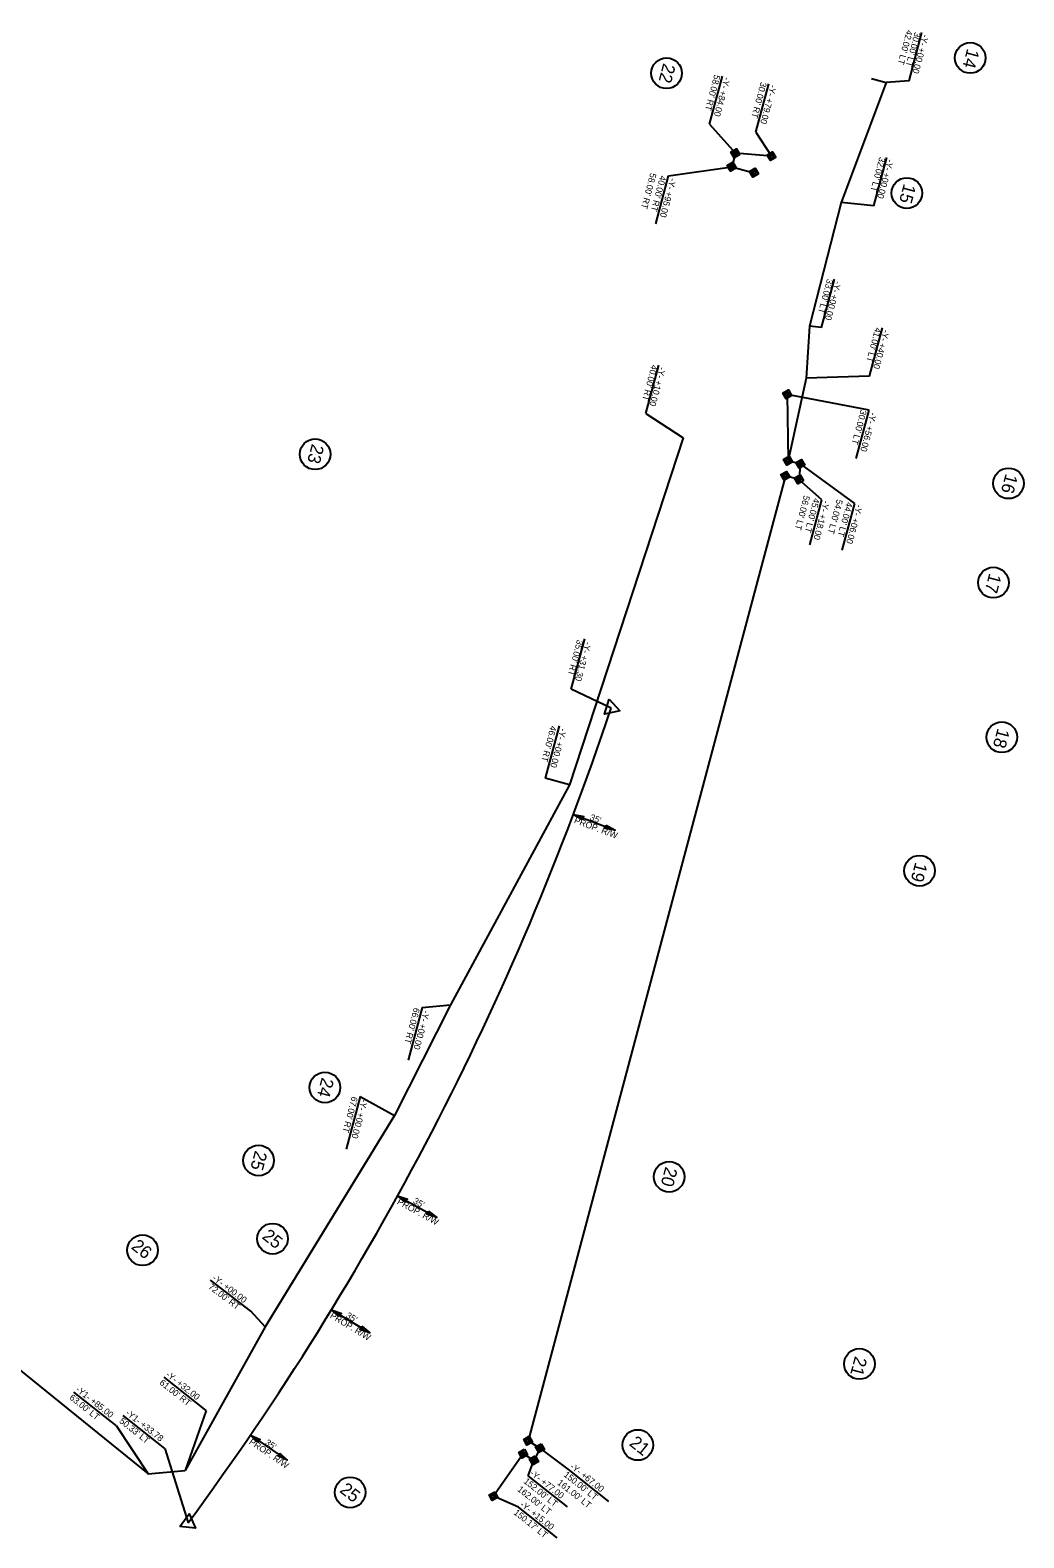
# Model space of a CAD drawing. Extents: x 1779796 to 1783527, y 810952 to 815815.
# Drawn here: x 1782441 to 1783220, y 814388 to 815570 of the extents above; entities that cross this region are included whole.
import ezdxf

# ---------------------------------------------------------------- set-up
doc = ezdxf.new("R2010")
doc.units = 0
for name, color, linetype in [('Prop Dimension', 7, 'Continuous'), ('Prop Dimension Text', 7, 'Continuous'), ('Prop Easement Construction', 7, 'Continuous'), ('Prop Easement Construction Station Offsets', 7, 'Continuous'), ('Prop Easement Permanent Utility', 7, 'Continuous'), ('Prop Easement Permanent Utility Station Offsets', 7, 'Continuous'), ('Prop Parcel Number CELL', 7, 'Continuous'), ('Prop Parcel Number Text', 7, 'Continuous'), ('Prop ROW Marker CELL', 7, 'Continuous'), ('Prop ROW Permanent Easement CELL', 7, 'Continuous'), ('Prop ROW RW Lines', 7, 'Continuous'), ('Prop ROW Station Offsets', 7, 'Continuous'), ('Prop Terminator CELL', 7, 'Continuous')]:
    doc.layers.add(name, color=color, linetype=linetype)

msp = doc.modelspace()

# ---------------------------------------------------------------- linework, layer by layer
at = {"layer": 'Prop Dimension'}
for p, q in [((1782866.5, 814955.2), (1782899.2, 814942.8)), ((1782728.7, 814656.4), (1782759.3, 814639.5)), ((1782676.9, 814567.2), (1782706.8, 814549)), ((1782613.3, 814468.9), (1782642.2, 814449.2))]:
    msp.add_line(p, q, dxfattribs=at)
at = {"layer": 'Prop Easement Construction'}
for p, q in [((1783100, 815531.7), (1783111.6, 815528.6)), ((1783111.6, 815528.6), (1783076.2, 815434.6)), ((1783076.2, 815434.6), (1783051.4, 815337.7)), ((1783051.4, 815337.7), (1783048.8, 815297)), ((1783048.8, 815297), (1783034.7, 815232.4)), ((1782952.5, 815250.2), (1782863.4, 814978.5)), ((1782863.4, 814978.5), (1782770, 814806)), ((1782770, 814806), (1782726.1, 814719.3)), ((1782726.1, 814719.3), (1782624.9, 814553.7)), ((1782354.4, 814583), (1782533.2, 814438.6)), ((1782624.9, 814553.7), (1782562.2, 814441.3)), ((1782533.2, 814438.6), (1782562.2, 814441.3))]:
    msp.add_line(p, q, dxfattribs=at)
at = {"layer": 'Prop Easement Construction Station Offsets'}
for p, q in [((1783129.5, 815530), (1783139.6, 815567.9)), ((1783129.5, 815530), (1783111.6, 815528.6)), ((1783101.9, 815432.1), (1783112, 815470)), ((1783101.9, 815432.1), (1783076.2, 815434.6)), ((1783060.9, 815336.7), (1783071, 815374.6)), ((1783060.9, 815336.7), (1783051.4, 815337.7)), ((1783098.6, 815298.5), (1783108.8, 815336.4)), ((1782923.3, 815269.4), (1782933.4, 815307.3)), ((1783098.6, 815298.5), (1783048.8, 815297)), ((1782923.3, 815269.4), (1782952.5, 815250.2)), ((1782855.2, 815024.7), (1782844.2, 814983.5)), ((1782863.4, 814978.5), (1782844.2, 814983.5)), ((1782748, 814803.9), (1782737, 814762.6)), ((1782748, 814803.9), (1782770, 814806)), ((1782699.4, 814734.2), (1782688.4, 814693)), ((1782699.4, 814734.2), (1782726.1, 814719.3)), ((1782613.7, 814566.1), (1782581.9, 814590.3)), ((1782624.9, 814553.7), (1782613.7, 814566.1)), ((1782578.6, 814488.2), (1782545.6, 814514.3)), ((1782508, 814476.5), (1782475, 814502.6)), ((1782578.6, 814488.2), (1782562.2, 814441.3))]:
    msp.add_line(p, q, dxfattribs=at)
msp.add_lwpolyline([(1782508, 814476.5), (1782533.2, 814438.6)], dxfattribs=at)
at = {"layer": 'Prop Easement Permanent Utility'}
for p, q in [((1782993.4, 815473.2), (1782990.5, 815462.6)), ((1783021.7, 815470.8), (1782993.4, 815473.2)), ((1782990.5, 815462.6), (1783007.9, 815457.9)), ((1783034.1, 815284.3), (1783034.7, 815232.4)), ((1783034.7, 815232.4), (1783044.4, 815229.8)), ((1783044.4, 815229.8), (1783043.2, 815217.7)), ((1783032.6, 815220.5), (1782830.9, 814464.5)), ((1783043.2, 815217.7), (1783032.6, 815220.5)), ((1782830.9, 814464.5), (1782840.3, 814458.7)), ((1782840.3, 814458.7), (1782835.5, 814449.1)), ((1782827, 814454.4), (1782803.9, 814421.2)), ((1782835.5, 814449.1), (1782827, 814454.4))]:
    msp.add_line(p, q, dxfattribs=at)
at = {"layer": 'Prop Easement Permanent Utility Station Offsets'}
for p, q in [((1782973.2, 815496), (1782983.2, 815533.5)), ((1783009.4, 815489.7), (1783019.5, 815527.6)), ((1782931, 815417.9), (1782941, 815455.4)), ((1783088.1, 815234.1), (1783098.2, 815272)), ((1783051.7, 815166.4), (1783061.1, 815201.8)), ((1783077.2, 815162.2), (1783086.9, 815198.7)), ((1782861.8, 814412.7), (1782831.1, 814437)), ((1782894.2, 814417), (1782862.4, 814442.2)), ((1782853.7, 814388.5), (1782823.3, 814412.5))]:
    msp.add_line(p, q, dxfattribs=at)
for points in [[(1782973.2, 815496), (1782993.4, 815473.2)], [(1783009.4, 815489.7), (1783021.7, 815470.8)], [(1782941, 815455.4), (1782990.5, 815462.6)], [(1783098.2, 815272), (1783034.1, 815284.3)], [(1783086.9, 815198.7), (1783044.4, 815229.8)], [(1783061.1, 815201.8), (1783043.2, 815217.7)], [(1782862.4, 814442.2), (1782840.3, 814458.7)], [(1782831.1, 814437), (1782835.5, 814449.1)], [(1782823.3, 814412.5), (1782803.9, 814421.2)]]:
    msp.add_lwpolyline(points, dxfattribs=at)
at = {"layer": 'Prop Parcel Number CELL'}
for p, q in [((1783177.5, 815547.9), (1783177.5, 815547.9)), ((1782939.5, 815535.9), (1782939.5, 815535.9)), ((1783127.8, 815442), (1783127.8, 815442)), ((1782664, 815237.4), (1782664, 815237.4)), ((1783207.5, 815214.6), (1783207.5, 815214.6)), ((1783195.6, 815136.8), (1783195.6, 815136.8)), ((1783202.2, 815015.7), (1783202.2, 815015.7)), ((1783137.8, 814911.1), (1783137.8, 814911.1)), ((1782671.7, 814741.3), (1782671.7, 814741.3)), ((1782619.7, 814684.1), (1782619.7, 814684.1)), ((1782941.5, 814671.3), (1782941.5, 814671.3)), ((1782630.7, 814622.8), (1782630.7, 814622.8)), ((1782528.8, 814613.8), (1782528.8, 814613.8)), ((1783090.6, 814524.7), (1783090.6, 814524.7)), ((1782916.9, 814461.2), (1782916.9, 814461.2)), ((1782691.5, 814424.1), (1782691.5, 814424.1))]:
    msp.add_line(p, q, dxfattribs=at)
for centre in [(1783177.5, 815547.9), (1782939.5, 815535.9), (1783127.8, 815442), (1782664, 815237.4), (1783207.5, 815214.6), (1783195.6, 815136.8), (1783202.2, 815015.7), (1783137.8, 814911.1), (1782671.7, 814741.3), (1782619.7, 814684.1), (1782941.5, 814671.3), (1782630.7, 814622.8), (1782528.8, 814613.8), (1783090.6, 814524.7), (1782916.9, 814461.2), (1782691.5, 814424.1)]:
    msp.add_circle(centre, 12, dxfattribs=at)
at = {"layer": 'Prop ROW Marker CELL'}
for p, q in [((1782993.4, 815473.2), (1782993.4, 815473.2)), ((1782990.5, 815462.6), (1782990.5, 815462.6)), ((1783021.7, 815470.8), (1783021.7, 815470.8)), ((1783007.9, 815457.9), (1783007.9, 815457.9)), ((1783034.1, 815284.3), (1783034.1, 815284.3)), ((1783034.7, 815232.4), (1783034.7, 815232.4)), ((1783044.4, 815229.8), (1783044.4, 815229.8)), ((1783032.6, 815220.5), (1783032.6, 815220.5)), ((1783043.2, 815217.7), (1783043.2, 815217.7)), ((1782896.1, 815038.5), (1782896.1, 815038.5)), ((1782830.9, 814464.5), (1782830.9, 814464.5)), ((1782840.3, 814458.7), (1782840.3, 814458.7)), ((1782827, 814454.4), (1782827, 814454.4)), ((1782835.5, 814449.1), (1782835.5, 814449.1)), ((1782803.9, 814421.2), (1782803.9, 814421.2)), ((1782564.5, 814400.3), (1782564.5, 814400.3))]:
    msp.add_line(p, q, dxfattribs=at)
for points in [[(1782894.5, 815045.6), (1782902.9, 815036.4), (1782890.8, 815033.7)], [(1782557.9, 814397.4), (1782565.3, 814407.4), (1782570.3, 814396)]]:
    msp.add_lwpolyline(points, close=True, dxfattribs=at)
at = {"layer": 'Prop ROW Permanent Easement CELL'}
for points in [[(1782996.8, 815472.3), (1782992.4, 815469.7), (1782989.9, 815474.1), (1782994.3, 815476.7)], [(1782995.1, 815472.7), (1782992.9, 815471.5), (1782991.6, 815473.7), (1782993.8, 815475)], [(1783025.2, 815469.9), (1783020.8, 815467.4), (1783018.2, 815471.8), (1783022.6, 815474.3)], [(1783023.4, 815470.4), (1783021.2, 815469.1), (1783020, 815471.3), (1783022.2, 815472.6)], [(1782994, 815461.7), (1782989.6, 815459.1), (1782987, 815463.5), (1782991.4, 815466.1)], [(1782992.3, 815462.1), (1782990.1, 815460.8), (1782988.8, 815463), (1782991, 815464.3)], [(1783011.4, 815457), (1783007, 815454.5), (1783004.4, 815458.9), (1783008.8, 815461.4)], [(1783009.6, 815457.5), (1783007.4, 815456.2), (1783006.2, 815458.4), (1783008.4, 815459.7)], [(1783037.5, 815283.4), (1783033.1, 815280.9), (1783030.6, 815285.3), (1783035, 815287.8)], [(1783035.8, 815283.9), (1783033.6, 815282.6), (1783032.3, 815284.8), (1783034.5, 815286.1)], [(1783038.2, 815231.5), (1783033.8, 815228.9), (1783031.2, 815233.3), (1783035.6, 815235.9)], [(1783036, 815219.6), (1783031.6, 815217.1), (1783029.1, 815221.5), (1783033.5, 815224)], [(1783036.4, 815231.9), (1783034.2, 815230.7), (1783033, 815232.9), (1783035.2, 815234.2)], [(1783047.8, 815228.9), (1783043.4, 815226.4), (1783040.9, 815230.8), (1783045.3, 815233.3)], [(1783046.1, 815229.4), (1783043.9, 815228.1), (1783042.6, 815230.3), (1783044.8, 815231.6)], [(1783034.3, 815220.1), (1783032.1, 815218.8), (1783030.8, 815221), (1783033, 815222.3)], [(1783046.7, 815216.8), (1783042.3, 815214.2), (1783039.7, 815218.6), (1783044.1, 815221.2)], [(1783044.9, 815217.2), (1783042.7, 815216), (1783041.4, 815218.2), (1783043.6, 815219.4)], [(1782831.9, 814468), (1782834.4, 814463.5), (1782830, 814461), (1782827.5, 814465.5)], [(1782828, 814457.9), (1782830.5, 814453.4), (1782826.1, 814450.9), (1782823.6, 814455.3)], [(1782827.5, 814456.1), (1782828.8, 814453.9), (1782826.6, 814452.7), (1782825.3, 814454.9)], [(1782831.4, 814466.2), (1782832.7, 814464), (1782830.5, 814462.8), (1782829.2, 814465)], [(1782841.3, 814462.2), (1782843.8, 814457.8), (1782839.3, 814455.3), (1782836.8, 814459.7)], [(1782840.8, 814460.5), (1782842, 814458.3), (1782839.8, 814457), (1782838.6, 814459.2)], [(1782836.5, 814452.6), (1782839, 814448.2), (1782834.6, 814445.6), (1782832.1, 814450.1)], [(1782836, 814450.8), (1782837.3, 814448.6), (1782835.1, 814447.4), (1782833.8, 814449.6)], [(1782804.8, 814424.6), (1782807.3, 814420.2), (1782802.9, 814417.7), (1782800.4, 814422.1)], [(1782804.3, 814422.9), (1782805.6, 814420.7), (1782803.4, 814419.4), (1782802.1, 814421.6)]]:
    msp.add_lwpolyline(points, close=True, dxfattribs=at)
at = {"layer": 'Prop ROW RW Lines'}
msp.add_arc((1780718.8, 815764.3), 2295, 323.5346, 341.5656, dxfattribs=at)
at = {"layer": 'Prop ROW Station Offsets'}
for p, q in [((1782864.8, 815053.3), (1782875.4, 815092.8)), ((1782896.1, 815038.5), (1782864.8, 815053.3)), ((1782546.3, 814458.4), (1782513.5, 814484.4))]:
    msp.add_line(p, q, dxfattribs=at)
msp.add_lwpolyline([(1782546.3, 814458.4), (1782564.5, 814400.3)], dxfattribs=at)
at = {"layer": 'Prop Terminator CELL'}
for points in [[(1782873.6, 814951), (1782866.5, 814955.2), (1782874.6, 814953.6), (1782873.1, 814952.6)], [(1782892, 814946.8), (1782899.2, 814942.8), (1782891.1, 814944.1), (1782892.5, 814945.2)], [(1782735.1, 814651.2), (1782728.7, 814656.4), (1782736.5, 814653.7), (1782734.9, 814652.9)], [(1782752.8, 814644.4), (1782759.3, 814639.5), (1782751.5, 814642), (1782753, 814642.8)], [(1782683.1, 814561.8), (1782676.9, 814567.2), (1782684.6, 814564.2), (1782683, 814563.5)], [(1782700.5, 814554.3), (1782706.8, 814549), (1782699, 814551.8), (1782700.6, 814552.6)], [(1782619.2, 814463.2), (1782613.3, 814468.9), (1782620.9, 814465.5), (1782619.2, 814464.9)], [(1782636.3, 814454.9), (1782642.2, 814449.2), (1782634.7, 814452.6), (1782636.3, 814453.2)]]:
    msp.add_lwpolyline(points, close=True, dxfattribs=at)

# ---------------------------------------------------------------- texts
at = {"layer": 'Prop Dimension Text'}
for s, rotation, p in [('PROP. R/W', 339.2959, (1782866.6, 814948.7)), ("35'", 339.2959, (1782878.9, 814951)), ('PROP. R/W', 331.0746, (1782727.8, 814650.4)), ("35'", 331.0746, (1782740.3, 814650.9)), ('PROP. R/W', 328.5015, (1782675.2, 814561.3)), ("35'", 328.5015, (1782687.7, 814561.4)), ('PROP. R/W', 325.5779, (1782611.8, 814462.6)), ("35'", 325.5779, (1782624.3, 814462))]:
    msp.add_text(s, height=5, rotation=rotation, dxfattribs=at).set_placement(p)
at = {"layer": 'Prop Easement Construction Station Offsets'}
for s, rotation, p in [("42.00' LT", 255.0684, (1783127.7, 815570.1)), ("30.00' LT", 255.0684, (1783133.9, 815568.4)), ('-Y- +00.00', 255.0684, (1783140.2, 815566.7)), ("32.00' LT", 255.0684, (1783106.3, 815470.5)), ('-Y- +00.00', 255.0684, (1783112.6, 815468.8)), ("33.00' LT", 255.0684, (1783065.3, 815375.1)), ('-Y- +00.00', 255.0684, (1783071.6, 815373.4)), ("41.00' LT", 255.0684, (1783103.1, 815337)), ('-Y- +40.00', 255.0684, (1783109.4, 815335.3)), ("40.00' RT", 255.0684, (1782927.7, 815307.8)), ('-Y- +10.00', 255.0684, (1782934, 815306.1)), ("46.00' RT", 255.0684, (1782848.6, 815025)), ('-Y- +00.00', 255.0684, (1782856.3, 815022.9)), ("66.00' RT", 255.0684, (1782741.4, 814804.1)), ('-Y- +00.00', 255.0684, (1782749.1, 814802.1)), ("67.00' RT", 255.0684, (1782692.8, 814734.5)), ('-Y- +00.00', 255.0684, (1782700.5, 814732.4)), ("72.00' RT", 322.799, (1782579.8, 814584.2)), ('-Y- +00.00', 322.799, (1782583.1, 814591)), ('-Y- +32.00', 321.6309, (1782546.6, 814515.5)), ('-Y1- +85.00', 321.6309, (1782476, 814503.8)), ("61.00' RT", 321.6309, (1782541.6, 814509.2)), ("63.00' LT", 321.6309, (1782471, 814497.5))]:
    msp.add_text(s, height=5, rotation=rotation, dxfattribs=at).set_placement(p)
at = {"layer": 'Prop Easement Permanent Utility Station Offsets'}
for s, rotation, p in [("58.00' RT", 255.0684, (1782976.9, 815535.1)), ('-Y- +84.00', 255.0684, (1782984.6, 815533.1)), ("30.00' RT", 255.0684, (1783013.2, 815529.3)), ('-Y- +79.00', 255.0684, (1783020.9, 815527.2)), ("58.00' RT", 255.0684, (1782926.8, 815458.1)), ("40.00' RT", 255.0684, (1782934.5, 815456.1)), ('-Y- +95.00', 255.0684, (1782942.2, 815454)), ("30.00' LT", 255.0684, (1783091.6, 815272.5)), ('-Y- +56.00', 255.0684, (1783099.4, 815270.5)), ("56.00' LT", 255.0684, (1783047.1, 815205.5)), ("45.00' LT", 255.0684, (1783054.8, 815203.4)), ('-Y- +18.00', 255.0684, (1783062.6, 815201.4)), ("54.00' LT", 255.0684, (1783072.9, 815202.4)), ("44.00' LT", 255.0684, (1783080.6, 815200.3)), ('-Y- +06.00', 255.0684, (1783088.3, 815198.3)), ('-Y- +67.00', 321.6309, (1782863.4, 814443.4)), ("152.00' LT", 321.6309, (1782827, 814431.9)), ('-Y- +77.00', 321.6309, (1782832, 814438.2)), ("161.00' LT", 321.6309, (1782853.4, 814430.8)), ("150.00' LT", 321.6309, (1782858.4, 814437.1)), ("162.00' LT", 321.6309, (1782822.1, 814425.6)), ("150.17' LT", 321.6309, (1782819.2, 814407.4)), ('-Y- +15.00', 321.6309, (1782824.2, 814413.7))]:
    msp.add_text(s, height=5, rotation=rotation, dxfattribs=at).set_placement(p)
at = {"layer": 'Prop Parcel Number Text'}
for s, rotation, p in [('14', 255.0673, (1783175.2, 815555.7)), ('22', 255.0673, (1782937, 815544.2)), ('15', 255.0673, (1783125.5, 815449.8)), ('23', 255.0673, (1782661.6, 815246)), ('16', 255.0673, (1783205.3, 815222.6)), ('17', 255.0673, (1783192.5, 815144.6)), ('18', 255.0673, (1783199, 815023.1)), ('19', 255.0673, (1783134.5, 814918.2)), ('24', 255.0673, (1782669.3, 814749.6)), ('25', 255.0673, (1782617, 814692.3)), ('20', 255.0673, (1782938.6, 814679.6)), ('26', 321.6309, (1782519.3, 814615.5)), ('25', 321.6309, (1782621.8, 814623.5)), ('21', 255.0673, (1783087.2, 814531.2)), ('21', 321.6309, (1782909.6, 814461.4)), ('25', 321.6309, (1782682.6, 814424.8))]:
    msp.add_text(s, height=10, rotation=rotation, dxfattribs=at).set_placement(p)
at = {"layer": 'Prop ROW Station Offsets'}
for s, rotation, p in [("35.00' RT", 255.0684, (1782869.4, 815092.4)), ('-Y- +31.30', 255.0684, (1782875.7, 815090.7)), ("50.33' LT", 321.6309, (1782510.1, 814479.1)), ('-Y1- +33.78', 321.6309, (1782515.1, 814485.4))]:
    msp.add_text(s, height=5, rotation=rotation, dxfattribs=at).set_placement(p)

doc.saveas('drawing.dxf')
